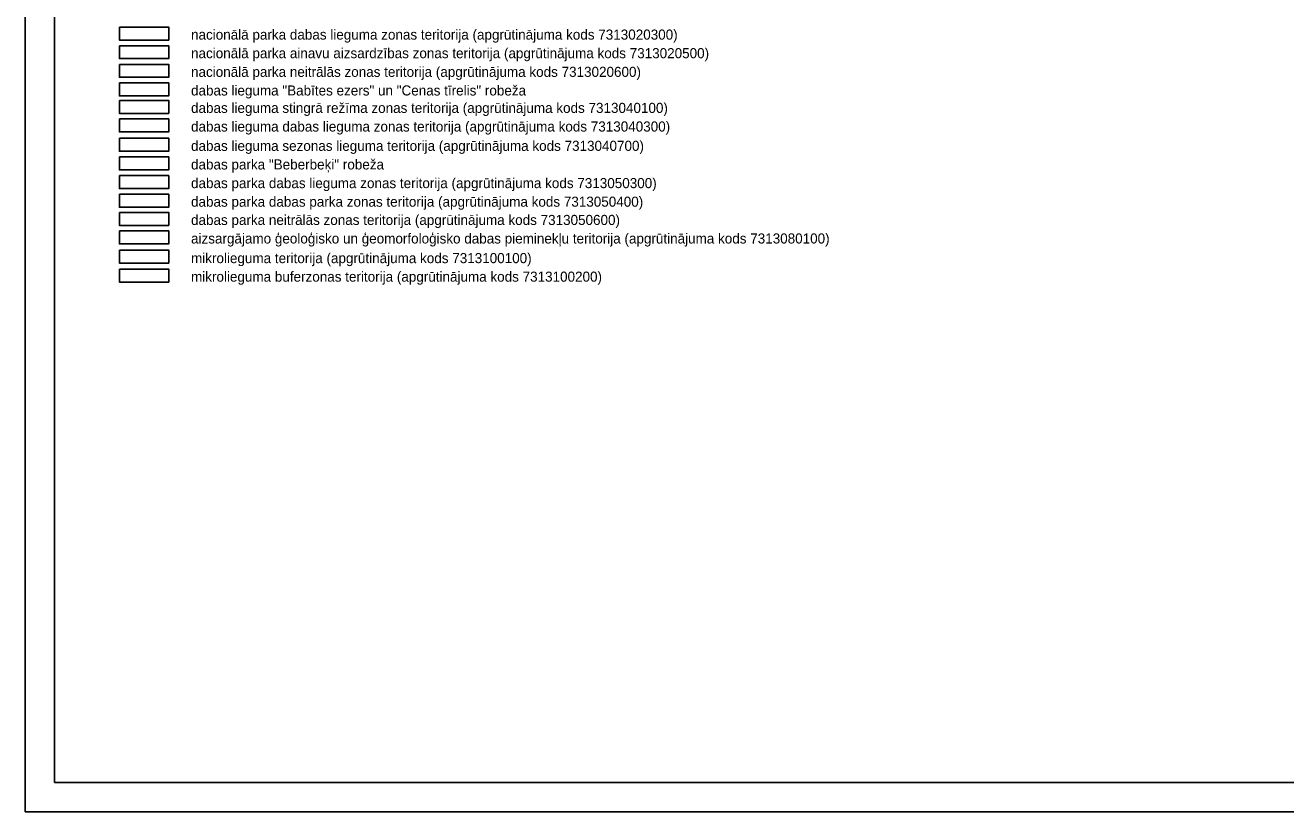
# Model space of a CAD drawing. Extents: x 468834 to 503362, y 294936 to 320859.
# Drawn here: x 468834 to 475323, y 294936 to 298982 of the extents above; entities that cross this region are included whole.
import ezdxf

# ---------------------------------------------------------------- set-up
doc = ezdxf.new("R2010")
doc.units = 0
for name, color, linetype in [('7313020300_nacionālā parka dabas lieguma zonas teritorija', 7, 'Continuous'), ('7313020500_nacionālā parka ainavu aizsardzības zonas teritorija', 7, 'Continuous'), ('7313020600_nacionālā parka neitrālās zonas teritorija', 7, 'Continuous'), ('7313040100_dabas lieguma stingrā režīma zonas teritorija', 7, 'Continuous'), ('7313040300_dabas lieguma dabas lieguma zonas teritorija', 7, 'Continuous'), ('7313040700_dabas lieguma sezonas lieguma teritorija', 7, 'Continuous'), ('7313050300_dabas parka dabas lieguma zonas teritorija', 7, 'Continuous'), ('7313050400_dabas parka dabas parka zonas teritorija', 7, 'Continuous'), ('7313050600_dabas parka neitrālās zonas teritorija', 7, 'Continuous'), ('7313080100_aizsargājamo ģeoloģisko un ģeomorfoloģisko dabas pieminekļu teritorija', 7, 'Continuous'), ('7313100100_mikrolieguma teritorija', 7, 'Continuous'), ('7313100200_mikrolieguma buferzonas teritorija', 7, 'Continuous'), ('Dabas lieguma robeža', 7, 'Continuous'), ('Dabas parka robeža', 7, 'Continuous'), ('ramis', 7, 'Continuous'), ('Teksts', 7, 'Continuous')]:
    doc.layers.add(name, color=color, linetype=linetype)

msp = doc.modelspace()

# ---------------------------------------------------------------- linework, layer by layer
at = {"layer": '7313020300_nacionālā parka dabas lieguma zonas teritorija'}
msp.add_lwpolyline([(469318.8, 298972.1), (469572.8, 298972.1), (469572.8, 298905.2), (469318.8, 298905.2)], close=True, dxfattribs=at)
at = {"layer": '7313020500_nacionālā parka ainavu aizsardzības zonas teritorija'}
msp.add_lwpolyline([(469318.8, 298876.4), (469572.8, 298876.4), (469572.8, 298809.6), (469318.8, 298809.6)], close=True, dxfattribs=at)
at = {"layer": '7313020600_nacionālā parka neitrālās zonas teritorija'}
msp.add_lwpolyline([(469318.8, 298780.4), (469572.8, 298780.4), (469572.8, 298713.6), (469318.8, 298713.6)], close=True, dxfattribs=at)
at = {"layer": '7313040100_dabas lieguma stingrā režīma zonas teritorija'}
msp.add_lwpolyline([(469318.8, 298595), (469572.8, 298595), (469572.8, 298528.2), (469318.8, 298528.2)], close=True, dxfattribs=at)
at = {"layer": '7313040300_dabas lieguma dabas lieguma zonas teritorija'}
msp.add_lwpolyline([(469318.8, 298499.4), (469572.8, 298499.4), (469572.8, 298432.5), (469318.8, 298432.5)], close=True, dxfattribs=at)
at = {"layer": '7313040700_dabas lieguma sezonas lieguma teritorija'}
msp.add_lwpolyline([(469318.8, 298399.9), (469572.8, 298399.9), (469572.8, 298333.1), (469318.8, 298333.1)], close=True, dxfattribs=at)
at = {"layer": '7313050300_dabas parka dabas lieguma zonas teritorija'}
msp.add_lwpolyline([(469318.8, 298208.3), (469572.8, 298208.3), (469572.8, 298141.4), (469318.8, 298141.4)], close=True, dxfattribs=at)
at = {"layer": '7313050400_dabas parka dabas parka zonas teritorija'}
msp.add_lwpolyline([(469318.8, 298112.6), (469572.8, 298112.6), (469572.8, 298045.8), (469318.8, 298045.8)], close=True, dxfattribs=at)
at = {"layer": '7313050600_dabas parka neitrālās zonas teritorija'}
msp.add_lwpolyline([(469318.8, 298018.8), (469572.8, 298018.8), (469572.8, 297952), (469318.8, 297952)], close=True, dxfattribs=at)
at = {"layer": '7313080100_aizsargājamo ģeoloģisko un ģeomorfoloģisko dabas pieminekļu teritorija'}
msp.add_lwpolyline([(469318.8, 297923.4), (469572.8, 297923.4), (469572.8, 297856.6), (469318.8, 297856.6)], close=True, dxfattribs=at)
at = {"layer": '7313100100_mikrolieguma teritorija'}
msp.add_lwpolyline([(469318.8, 297825.2), (469572.8, 297825.2), (469572.8, 297758.4), (469318.8, 297758.4)], close=True, dxfattribs=at)
at = {"layer": '7313100200_mikrolieguma buferzonas teritorija'}
msp.add_lwpolyline([(469318.8, 297727), (469572.8, 297727), (469572.8, 297660.2), (469318.8, 297660.2)], close=True, dxfattribs=at)
at = {"layer": 'Dabas lieguma robeža'}
msp.add_lwpolyline([(469318.8, 298684.8), (469572.8, 298684.8), (469572.8, 298617.9), (469318.8, 298617.9)], close=True, dxfattribs=at)
at = {"layer": 'Dabas parka robeža'}
msp.add_lwpolyline([(469318.8, 298304.3), (469572.8, 298304.3), (469572.8, 298237.4), (469318.8, 298237.4)], close=True, dxfattribs=at)
at = {"layer": 'ramis'}
for p, q in [((468983.8, 295086.2), (468983.8, 316660.3)), ((500923.3, 295086.2), (468983.8, 295086.2))]:
    msp.add_line(p, q, dxfattribs=at)
msp.add_lwpolyline([(501073.3, 316810.3), (468833.8, 316810.3), (468833.8, 294936.2), (501073.3, 294936.2)], close=True, dxfattribs=at)

# ---------------------------------------------------------------- texts
at = {"layer": 'Teksts'}
for s, p in [('nacionālā parka dabas lieguma zonas teritorija (apgrūtinājuma kods 7313020300)', (469687.4, 298907.5)), ('nacionālā parka ainavu aizsardzības zonas teritorija (apgrūtinājuma kods 7313020500)', (469687.4, 298811.9)), ('nacionālā parka neitrālās zonas teritorija (apgrūtinājuma kods 7313020600)', (469687.4, 298715.9)), ('dabas lieguma "Babītes ezers" un "Cenas tīrelis" robeža', (469687.4, 298620.2)), ('dabas lieguma stingrā režīma zonas teritorija (apgrūtinājuma kods 7313040100)', (469687.4, 298530.5)), ('dabas lieguma dabas lieguma zonas teritorija (apgrūtinājuma kods 7313040300)', (469687.4, 298434.8)), ('dabas lieguma sezonas lieguma teritorija (apgrūtinājuma kods 7313040700)', (469687.4, 298335.4)), ('dabas parka "Beberbeķi" robeža', (469687.4, 298239.7)), ('dabas parka dabas lieguma zonas teritorija (apgrūtinājuma kods 7313050300)', (469687.4, 298143.7)), ('dabas parka dabas parka zonas teritorija (apgrūtinājuma kods 7313050400)', (469687.4, 298048.1)), ('dabas parka neitrālās zonas teritorija (apgrūtinājuma kods 7313050600)', (469687.4, 297954.2)), ('aizsargājamo ģeoloģisko un ģeomorfoloģisko dabas pieminekļu teritorija (apgrūtinājuma kods 7313080100)', (469687.4, 297858.9)), ('mikrolieguma teritorija (apgrūtinājuma kods 7313100100)', (469687.4, 297757.9)), ('mikrolieguma buferzonas teritorija (apgrūtinājuma kods 7313100200)', (469687.4, 297662.5))]:
    msp.add_text(s, height=51.84, dxfattribs=at).set_placement(p)

doc.saveas('drawing.dxf')
